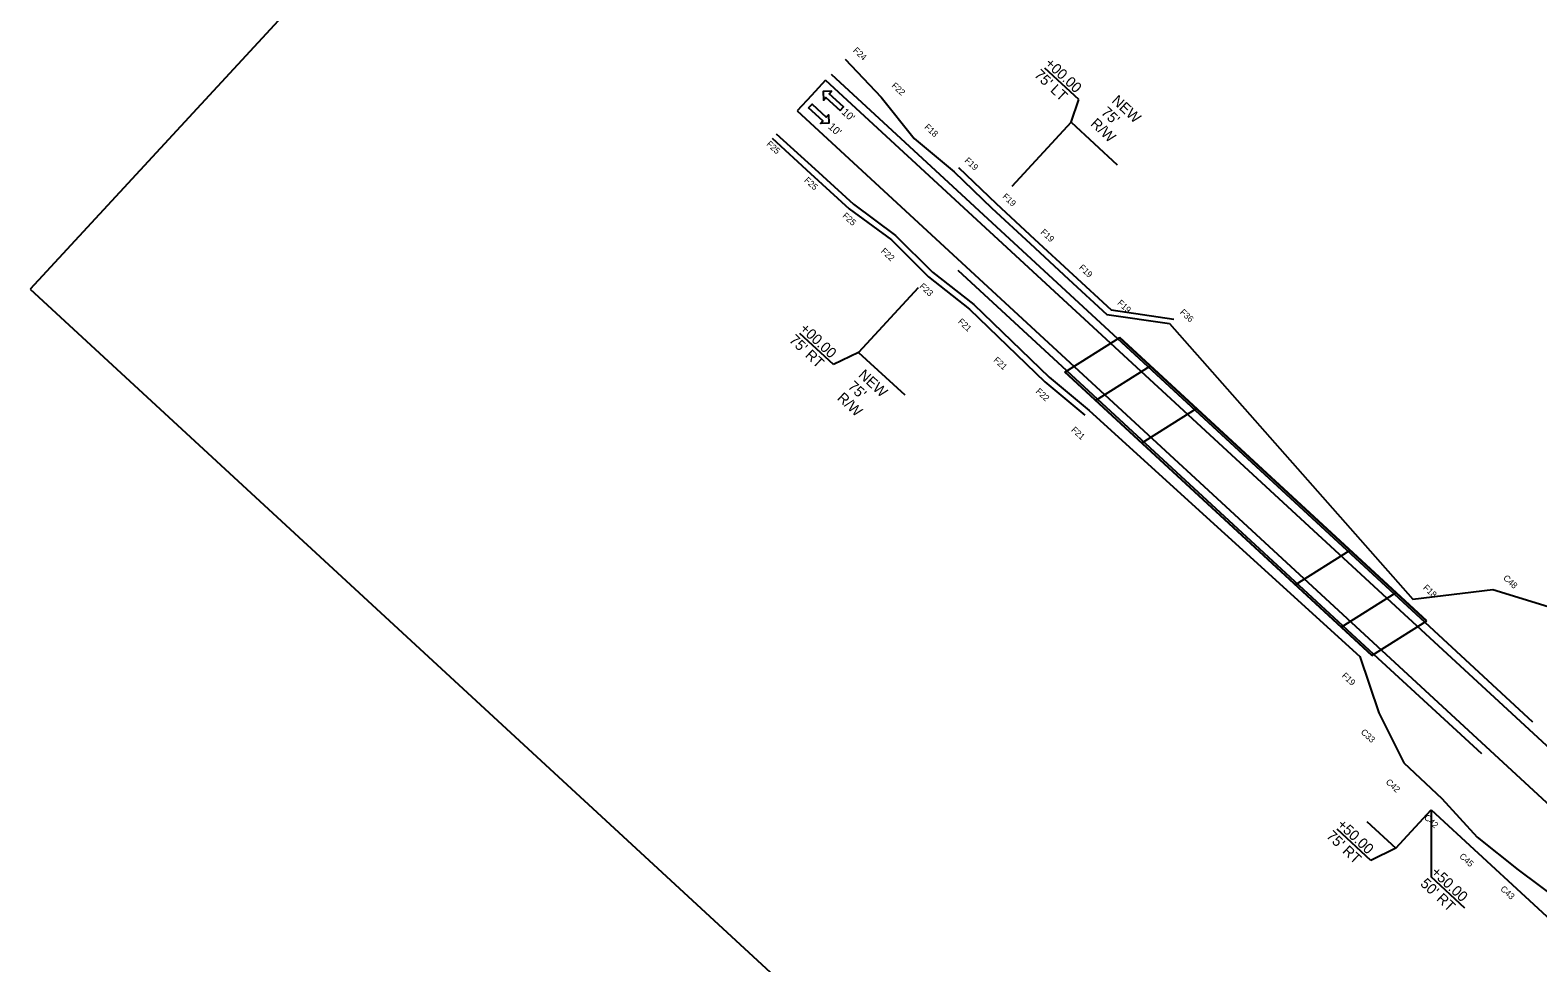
# Model space of a CAD drawing. Extents: x 1877044 to 1878285, y 1204828 to 1206046.
# Drawn here: x 1877044 to 1877765, y 1205238 to 1205685 of the extents above; entities that cross this region are included whole.
import ezdxf

# ---------------------------------------------------------------- set-up
doc = ezdxf.new("R2010")
doc.units = 0
for name, color, linetype in [('Default', 7, 'Continuous'), ('RD_PD_Bridge', 7, 'Continuous'), ('RD_PD_CstnLmt', 7, 'Continuous'), ('RD_PD_CstnLmt_TX', 7, 'Continuous'), ('RD_PD_DR_ErosCtrl', 7, 'Continuous'), ('RD_PD_Final_TrvlWay', 7, 'Continuous'), ('RD_PD_Final_TX', 7, 'Continuous'), ('RD_PD_GR', 7, 'Continuous'), ('RD_PD_RW', 7, 'Continuous'), ('RD_PD_RW_TX', 7, 'Continuous'), ('RD_SHT_TX', 7, 'Continuous'), ('RD_Sketch2', 7, 'Continuous')]:
    doc.layers.add(name, color=color, linetype=linetype)

msp = doc.modelspace()

# ---------------------------------------------------------------- linework, layer by layer
at = {"layer": 'Default'}
for p, q in [((1877538.88, 1205520.94), (1877565.14, 1205537.52)), ((1877712.06, 1205401.83), (1877565.14, 1205537.52)), ((1877685.8, 1205385.24), (1877538.88, 1205520.94))]:
    msp.add_line(p, q, dxfattribs=at)
at = {"layer": 'RD_PD_Bridge'}
for p, q in [((1877538.88, 1205520.94), (1877565.14, 1205537.52)), ((1877711.12, 1205401.23), (1877564.19, 1205536.92)), ((1877711.99, 1205401.78), (1877565.06, 1205537.48)), ((1877685.88, 1205385.29), (1877538.95, 1205520.98)), ((1877686.75, 1205385.84), (1877539.82, 1205521.54)), ((1877553.57, 1205507.37), (1877579.83, 1205523.95)), ((1877575.61, 1205487.01), (1877601.87, 1205503.6)), ((1877649.07, 1205419.17), (1877675.33, 1205435.75)), ((1877671.11, 1205398.81), (1877697.37, 1205415.4)), ((1877685.8, 1205385.24), (1877712.06, 1205401.83))]:
    msp.add_line(p, q, dxfattribs=at)
at = {"layer": 'RD_PD_CstnLmt'}
for p, q in [((1877433.63, 1205670.78), (1877450.92, 1205652.66)), ((1877450.92, 1205652.66), (1877466.65, 1205632.84)), ((1877400.73, 1205635.16), (1877419.16, 1205618.27)), ((1877466.65, 1205632.84), (1877485.89, 1205616.82)), ((1877419.16, 1205618.27), (1877437.65, 1205601.44)), ((1877485.89, 1205616.82), (1877503.97, 1205599.55)), ((1877437.65, 1205601.44), (1877457.87, 1205586.48)), ((1877503.97, 1205599.55), (1877522.26, 1205582.51)), ((1877457.87, 1205586.48), (1877475.57, 1205568.8)), ((1877522.26, 1205582.51), (1877540.6, 1205565.51)), ((1877475.57, 1205568.8), (1877495.31, 1205553.32)), ((1877540.6, 1205565.51), (1877559.01, 1205548.61)), ((1877495.31, 1205553.32), (1877513.3, 1205535.96)), ((1877559.01, 1205548.61), (1877588.96, 1205544.19)), ((1877588.96, 1205544.19), (1877705.33, 1205412.25)), ((1877513.3, 1205535.96), (1877531.27, 1205518.57)), ((1877531.27, 1205518.57), (1877550.51, 1205502.55)), ((1877550.51, 1205502.55), (1877679.99, 1205384.81)), ((1877705.33, 1205412.25), (1877743.65, 1205416.9)), ((1877743.65, 1205416.9), (1877770.21, 1205408.81)), ((1877679.99, 1205384.81), (1877689.06, 1205357.79)), ((1877689.06, 1205357.79), (1877701.03, 1205333.91)), ((1877701.03, 1205333.91), (1877719.35, 1205316.89)), ((1877719.35, 1205316.89), (1877736.26, 1205298.35)), ((1877736.26, 1205298.35), (1877755.86, 1205282.72)), ((1877755.86, 1205282.72), (1877775.99, 1205267.67))]:
    msp.add_line(p, q, dxfattribs=at)
at = {"layer": 'RD_PD_DR_ErosCtrl'}
for points in [[(1877398.7, 1205632.95), (1877417.13, 1205616.06), (1877435.62, 1205599.24), (1877455.83, 1205584.28), (1877473.54, 1205566.6), (1877493.27, 1205551.12), (1877511.26, 1205533.75), (1877529.24, 1205516.37), (1877548.47, 1205500.35)], [(1877487.92, 1205619.02), (1877506.01, 1205601.76), (1877524.29, 1205584.71), (1877542.63, 1205567.72), (1877561.05, 1205550.81), (1877591, 1205546.39)]]:
    msp.add_lwpolyline(points, dxfattribs=at)
at = {"layer": 'RD_PD_Final_TrvlWay'}
for p, q in [((1877424.35, 1205660.73), (1877829.65, 1205286.43)), ((1877410.78, 1205646.04), (1877816.08, 1205271.74))]:
    msp.add_line(p, q, dxfattribs=at)
msp.add_lwpolyline([(1877424.35, 1205660.73), (1877417.57, 1205653.39), (1877410.78, 1205646.04)], dxfattribs=at)
at = {"layer": 'RD_PD_Final_TX'}
for points in [[(1877431.24, 1205646.28), (1877432.87, 1205648.05), (1877426.1, 1205654.25), (1877427.2, 1205655.45), (1877423.21, 1205655.28), (1877423.38, 1205651.28), (1877424.48, 1205652.48)], [(1877416.23, 1205647.49), (1877417.86, 1205649.25), (1877424.58, 1205643), (1877425.69, 1205644.19), (1877425.83, 1205640.2), (1877421.83, 1205640.05), (1877422.94, 1205641.25)]]:
    msp.add_lwpolyline(points, close=True, dxfattribs=at)
at = {"layer": 'RD_PD_GR'}
for p, q in [((1877427.01, 1205663.61), (1877564.19, 1205536.92)), ((1877539.82, 1205521.54), (1877487.76, 1205569.62)), ((1877711.12, 1205401.23), (1877762.69, 1205353.6)), ((1877738.38, 1205338.16), (1877686.75, 1205385.84))]:
    msp.add_line(p, q, dxfattribs=at)
at = {"layer": 'RD_PD_RW'}
for p, q in [((1877541.91, 1205640.64), (1877513.42, 1205609.79)), ((1877541.91, 1205640.64), (1877563.96, 1205620.28)), ((1877468.64, 1205561.3), (1877440.15, 1205530.44)), ((1877440.15, 1205530.44), (1877462.19, 1205510.09)), ((1877697.27, 1205292.98), (1877714.23, 1205311.35)), ((1877714.23, 1205311.35), (1877788.94, 1205242.35)), ((1877683.31, 1205305.88), (1877697.27, 1205292.98))]:
    msp.add_line(p, q, dxfattribs=at)
at = {"layer": 'RD_PD_RW_TX'}
for p, q in [((1877545.47, 1205651.6), (1877529.3, 1205666.54)), ((1877541.91, 1205640.64), (1877545.47, 1205651.6)), ((1877428.12, 1205524.57), (1877411.98, 1205539.54)), ((1877440.15, 1205530.44), (1877428.12, 1205524.57)), ((1877714.23, 1205311.35), (1877714.13, 1205279.25)), ((1877685.24, 1205287.11), (1877669.11, 1205302.08)), ((1877697.27, 1205292.98), (1877685.24, 1205287.11)), ((1877730.27, 1205264.27), (1877714.13, 1205279.25))]:
    msp.add_line(p, q, dxfattribs=at)
at = {"layer": 'RD_Sketch2'}
msp.add_lwpolyline([(1877043.62, 1205560.73), (1877837.06, 1204828.03), (1878284.82, 1205312.91), (1877491.38, 1206045.61)], close=True, dxfattribs=at)

# ---------------------------------------------------------------- texts
at = {"layer": 'RD_PD_CstnLmt_TX'}
for s, p in [('F24', (1877437.23, 1205674.68)), ('F22', (1877455.67, 1205657.8)), ('F18', (1877471.4, 1205637.98)), ('F25', (1877395.81, 1205629.83)), ('F19', (1877490.64, 1205621.96)), ('F25', (1877413.87, 1205612.53)), ('F19', (1877508.72, 1205604.7)), ('F25', (1877432.18, 1205595.52)), ('F19', (1877527.01, 1205587.65)), ('F22', (1877450.56, 1205578.56)), ('F19', (1877545.34, 1205570.66)), ('F23', (1877469.04, 1205561.73)), ('F19', (1877563.76, 1205553.75)), ('F21', (1877487.44, 1205544.8)), ('F36', (1877593.71, 1205549.33)), ('F21', (1877504.48, 1205526.41)), ('F22', (1877524.69, 1205511.45)), ('F21', (1877541.69, 1205493)), ('C48', (1877748.4, 1205422.04)), ('F18', (1877710.08, 1205417.4)), ('F19', (1877671.17, 1205375.26)), ('C33', (1877680.24, 1205348.24)), ('C42', (1877692.21, 1205324.36)), ('C42', (1877710.53, 1205307.34)), ('C45', (1877727.44, 1205288.8)), ('C43', (1877747.04, 1205273.17))]:
    msp.add_text(s, height=3, rotation=317.27672, dxfattribs=at).set_placement(p)
at = {"layer": 'RD_PD_RW_TX'}
for s, rotation, p in [('+00.00', 317.07125, (1877528.92, 1205668.33)), ("75' LT", 317.07125, (1877523.81, 1205662.83)), ("75'", 317.27908, (1877555.86, 1205644.92)), ('NEW', 317.27908, (1877560.94, 1205650.43)), ('R/W', 317.27908, (1877550.77, 1205639.41)), ("75' RT", 316.93656, (1877406.49, 1205535.85)), ('+00.00', 316.93656, (1877411.61, 1205541.33)), ('NEW', 317.27908, (1877439.69, 1205519.13)), ('R/W', 317.27908, (1877429.51, 1205508.11)), ("75'", 317.27908, (1877434.6, 1205513.62)), ("75' RT", 316.93656, (1877663.61, 1205298.39)), ('+50.00', 316.93656, (1877668.73, 1205303.87)), ('+50.00', 316.93656, (1877713.76, 1205281.04)), ("50' RT", 316.93656, (1877708.64, 1205275.56))]:
    msp.add_text(s, height=5, rotation=rotation, dxfattribs=at).set_placement(p)
at = {"layer": 'RD_SHT_TX'}
for p in [(1877431.7, 1205644.98), (1877425.27, 1205638.01)]:
    msp.add_text("10'", height=3.6, rotation=318.36688, dxfattribs=at).set_placement(p)

doc.saveas('drawing.dxf')
